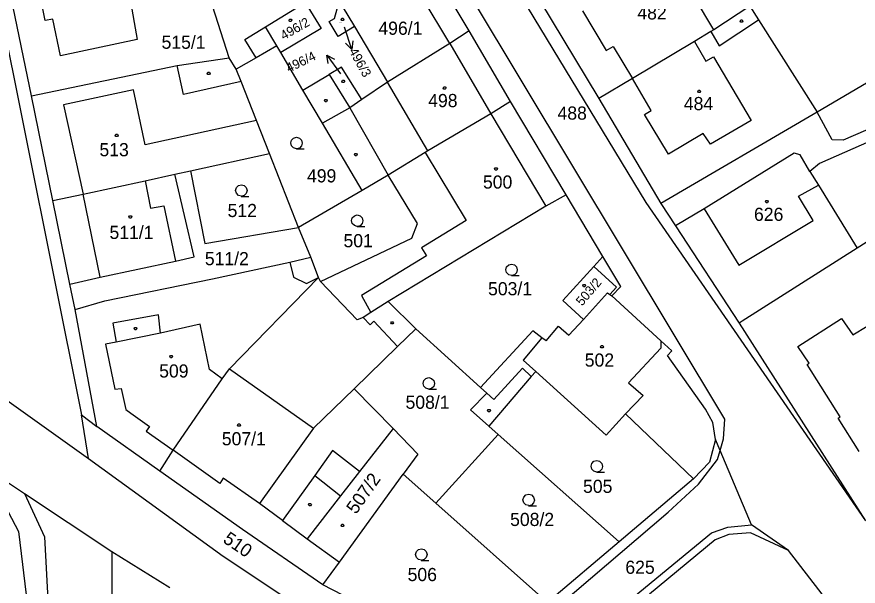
# Model space of a CAD drawing. Extents: x -621797 to -620972, y -1175539 to -1174697.
# Drawn here: x -621483.9 to -621375.1, y -1174942.7 to -1174869.1 of the extents above; entities that cross this region are included whole.
import ezdxf

# ---------------------------------------------------------------- set-up
doc = ezdxf.new("R2010")
doc.units = 0
for name, color, linetype in [('INZ mimo EON - nadz', 7, 'Continuous'), ('Rozvod plynu EON', 7, 'Continuous'), ('SDEL EON', 7, 'Continuous'), ('SDEL EON - popis', 7, 'Continuous'), ('Silnoproud EON', 7, 'Continuous'), ('Silnoproud EON - popis', 7, 'Continuous')]:
    doc.layers.add(name, color=color, linetype=linetype)

msp = doc.modelspace()

# ---------------------------------------------------------------- linework, layer by layer
at = {"layer": 'INZ mimo EON - nadz'}
for p, q in [((-621440.592, -1174873.333), (-621441.52, -1174870.48)), ((-621443.803, -1174874.072), (-621442.04, -1174876.5))]:
    msp.add_line(p, q, dxfattribs=at)
for points in [[(-621440.426, -1174872.227), (-621440.592, -1174873.333), (-621441.377, -1174872.537)], [(-621443.62, -1174875.175), (-621443.803, -1174874.072), (-621442.81, -1174874.588)]]:
    msp.add_lwpolyline(points, dxfattribs=at)
at = {"layer": 'Rozvod plynu EON'}
for points in [[(-621441.7, -1174869.31), (-621441.61, -1174869.46), (-621441.7, -1174869.61), (-621441.88, -1174869.61), (-621441.97, -1174869.46), (-621441.88, -1174869.31)], [(-621448.43, -1174869.43), (-621448.34, -1174869.58), (-621448.43, -1174869.73), (-621448.61, -1174869.73), (-621448.7, -1174869.58), (-621448.61, -1174869.43)], [(-621390.1, -1174869.53), (-621390.01, -1174869.68), (-621390.1, -1174869.83), (-621390.28, -1174869.83), (-621390.37, -1174869.68), (-621390.28, -1174869.53)], [(-621458.99, -1174876.29), (-621458.9, -1174876.44), (-621458.99, -1174876.59), (-621459.17, -1174876.59), (-621459.26, -1174876.44), (-621459.17, -1174876.29)], [(-621441.59, -1174877.32), (-621441.5, -1174877.47), (-621441.59, -1174877.62), (-621441.77, -1174877.62), (-621441.86, -1174877.47), (-621441.77, -1174877.32)], [(-621428.49, -1174878.19), (-621428.4, -1174878.34), (-621428.49, -1174878.49), (-621428.67, -1174878.49), (-621428.76, -1174878.34), (-621428.67, -1174878.19)], [(-621395.59, -1174878.61), (-621395.5, -1174878.76), (-621395.59, -1174878.91), (-621395.77, -1174878.91), (-621395.86, -1174878.76), (-621395.77, -1174878.61)], [(-621443.84, -1174879.81), (-621443.75, -1174879.96), (-621443.84, -1174880.11), (-621444.02, -1174880.11), (-621444.11, -1174879.96), (-621444.02, -1174879.81)], [(-621470.89, -1174884.3), (-621470.8, -1174884.45), (-621470.89, -1174884.6), (-621471.07, -1174884.6), (-621471.16, -1174884.45), (-621471.07, -1174884.3)], [(-621439.98, -1174886.79), (-621439.89, -1174886.94), (-621439.98, -1174887.09), (-621440.16, -1174887.09), (-621440.25, -1174886.94), (-621440.16, -1174886.79)], [(-621421.85, -1174888.63), (-621421.76, -1174888.78), (-621421.85, -1174888.93), (-621422.03, -1174888.93), (-621422.12, -1174888.78), (-621422.03, -1174888.63)], [(-621386.83, -1174892.85), (-621386.74, -1174893), (-621386.83, -1174893.15), (-621387.01, -1174893.15), (-621387.1, -1174893), (-621387.01, -1174892.85)], [(-621469.12, -1174894.83), (-621469.03, -1174894.98), (-621469.12, -1174895.13), (-621469.3, -1174895.13), (-621469.39, -1174894.98), (-621469.3, -1174894.83)], [(-621410.46, -1174903.71), (-621410.37, -1174903.86), (-621410.46, -1174904.01), (-621410.64, -1174904.01), (-621410.73, -1174903.86), (-621410.64, -1174903.71)], [(-621468.44, -1174909.27), (-621468.35, -1174909.42), (-621468.44, -1174909.57), (-621468.62, -1174909.57), (-621468.71, -1174909.42), (-621468.62, -1174909.27)], [(-621435.26, -1174908.53), (-621435.17, -1174908.68), (-621435.26, -1174908.83), (-621435.44, -1174908.83), (-621435.53, -1174908.68), (-621435.44, -1174908.53)], [(-621408.14, -1174911.62), (-621408.05, -1174911.77), (-621408.14, -1174911.92), (-621408.32, -1174911.92), (-621408.41, -1174911.77), (-621408.32, -1174911.62)], [(-621463.83, -1174912.89), (-621463.74, -1174913.04), (-621463.83, -1174913.19), (-621464.01, -1174913.19), (-621464.1, -1174913.04), (-621464.01, -1174912.89)], [(-621422.75, -1174919.88), (-621422.66, -1174920.03), (-621422.75, -1174920.18), (-621422.93, -1174920.18), (-621423.02, -1174920.03), (-621422.93, -1174919.88)], [(-621455.07, -1174921.75), (-621454.98, -1174921.9), (-621455.07, -1174922.05), (-621455.25, -1174922.05), (-621455.34, -1174921.9), (-621455.25, -1174921.75)], [(-621445.9, -1174932.03), (-621445.81, -1174932.18), (-621445.9, -1174932.33), (-621446.08, -1174932.33), (-621446.17, -1174932.18), (-621446.08, -1174932.03)], [(-621441.68, -1174934.72), (-621441.59, -1174934.87), (-621441.68, -1174935.02), (-621441.86, -1174935.02), (-621441.95, -1174934.87), (-621441.86, -1174934.72)]]:
    msp.add_lwpolyline(points, close=True, dxfattribs=at)
at = {"layer": 'SDEL EON'}
for points in [[(-621447.72, -1174886.17), (-621448.1, -1174886.07), (-621448.37, -1174885.8), (-621448.47, -1174885.43), (-621448.37, -1174885.06), (-621448.1, -1174884.79), (-621447.73, -1174884.69), (-621447.36, -1174884.79), (-621447.09, -1174885.06), (-621446.99, -1174885.44), (-621447.09, -1174885.82), (-621447.36, -1174886.09), (-621447.74, -1174886.19), (-621446.74, -1174886.19)], [(-621454.85, -1174892.31), (-621455.23, -1174892.21), (-621455.5, -1174891.94), (-621455.6, -1174891.57), (-621455.5, -1174891.2), (-621455.23, -1174890.93), (-621454.86, -1174890.83), (-621454.49, -1174890.93), (-621454.22, -1174891.2), (-621454.12, -1174891.58), (-621454.22, -1174891.96), (-621454.49, -1174892.23), (-621454.87, -1174892.33), (-621453.87, -1174892.33)], [(-621439.87, -1174896.21), (-621440.25, -1174896.11), (-621440.52, -1174895.84), (-621440.62, -1174895.47), (-621440.52, -1174895.1), (-621440.25, -1174894.83), (-621439.88, -1174894.73), (-621439.51, -1174894.83), (-621439.24, -1174895.1), (-621439.14, -1174895.48), (-621439.24, -1174895.86), (-621439.51, -1174896.13), (-621439.89, -1174896.23), (-621438.89, -1174896.23)], [(-621419.91, -1174902.56), (-621420.29, -1174902.46), (-621420.56, -1174902.19), (-621420.66, -1174901.82), (-621420.56, -1174901.45), (-621420.29, -1174901.18), (-621419.92, -1174901.08), (-621419.55, -1174901.18), (-621419.28, -1174901.45), (-621419.18, -1174901.83), (-621419.28, -1174902.21), (-621419.55, -1174902.48), (-621419.93, -1174902.58), (-621418.93, -1174902.58)], [(-621430.62, -1174917.24), (-621431, -1174917.14), (-621431.27, -1174916.87), (-621431.37, -1174916.5), (-621431.27, -1174916.13), (-621431, -1174915.86), (-621430.63, -1174915.76), (-621430.26, -1174915.86), (-621429.99, -1174916.13), (-621429.89, -1174916.51), (-621429.99, -1174916.89), (-621430.26, -1174917.16), (-621430.64, -1174917.26), (-621429.64, -1174917.26)], [(-621408.9, -1174927.96), (-621409.28, -1174927.86), (-621409.55, -1174927.59), (-621409.65, -1174927.22), (-621409.55, -1174926.85), (-621409.28, -1174926.58), (-621408.91, -1174926.48), (-621408.54, -1174926.58), (-621408.27, -1174926.85), (-621408.17, -1174927.23), (-621408.27, -1174927.61), (-621408.54, -1174927.88), (-621408.92, -1174927.98), (-621407.92, -1174927.98)], [(-621417.7, -1174932.31), (-621418.08, -1174932.21), (-621418.35, -1174931.94), (-621418.45, -1174931.57), (-621418.35, -1174931.2), (-621418.08, -1174930.93), (-621417.71, -1174930.83), (-621417.34, -1174930.93), (-621417.07, -1174931.2), (-621416.97, -1174931.58), (-621417.07, -1174931.96), (-621417.34, -1174932.23), (-621417.72, -1174932.33), (-621416.72, -1174932.33)], [(-621431.58, -1174939.36), (-621431.96, -1174939.26), (-621432.23, -1174938.99), (-621432.33, -1174938.62), (-621432.23, -1174938.25), (-621431.96, -1174937.98), (-621431.59, -1174937.88), (-621431.22, -1174937.98), (-621430.95, -1174938.25), (-621430.85, -1174938.63), (-621430.95, -1174939.01), (-621431.22, -1174939.28), (-621431.6, -1174939.38), (-621430.6, -1174939.38)]]:
    msp.add_lwpolyline(points, dxfattribs=at)
at = {"layer": 'SDEL EON - popis'}
for p, q in [((-621461.85, -1174795.25), (-621402.58, -1174893.11)), ((-621392.36, -1174921.13), (-621457.84, -1174812.05)), ((-621496.37, -1174817.09), (-621475.54, -1174920.55)), ((-621393.76, -1174870.81), (-621400.21, -1174860.03)), ((-621427.89, -1174872.59), (-621432.38, -1174865.12)), ((-621410.77, -1174868.36), (-621407.68, -1174873.5)), ((-621450.25, -1174872.87), (-621451.73, -1174870.41)), ((-621440.25, -1174870.4), (-621435.96, -1174877.59)), ((-621393.09, -1174872.86), (-621387.99, -1174869.52)), ((-621394.15, -1174871.04), (-621393.09, -1174872.86)), ((-621427.89, -1174872.59), (-621422.62, -1174881.67)), ((-621396.27, -1174872.3), (-621394.83, -1174874.88)), ((-621407.68, -1174873.5), (-621406.78, -1174872.96)), ((-621406.78, -1174872.96), (-621404.31, -1174877.11)), ((-621394.83, -1174874.88), (-621393.84, -1174874.3)), ((-621393.84, -1174874.3), (-621388.96, -1174882.51)), ((-621462.33, -1174879.15), (-621463.14, -1174875.44)), ((-621446.9, -1174878.59), (-621443.51, -1174876.59)), ((-621454.89, -1174877.5), (-621462.33, -1174879.15)), ((-621430.75, -1174886.47), (-621435.96, -1174877.59)), ((-621401.87, -1174881.25), (-621404.31, -1174877.11)), ((-621468.79, -1174878.58), (-621477.87, -1174880.51)), ((-621467.28, -1174885.68), (-621468.79, -1174878.58)), ((-621477.87, -1174880.51), (-621475.29, -1174892.05)), ((-621440.85, -1174880.87), (-621435.89, -1174889.58)), ((-621402.75, -1174881.74), (-621401.87, -1174881.25)), ((-621422.62, -1174881.67), (-621415.51, -1174893.59)), ((-621399.63, -1174886.87), (-621402.75, -1174881.74)), ((-621452.92, -1174882.52), (-621467.28, -1174885.68)), ((-621388.96, -1174882.51), (-621394.22, -1174885.59)), ((-621395.15, -1174884.2), (-621399.63, -1174886.87)), ((-621394.22, -1174885.59), (-621395.15, -1174884.2)), ((-621431.09, -1174886.68), (-621425.81, -1174895.47)), ((-621467.31, -1174890.31), (-621466.6, -1174893.88)), ((-621382.81, -1174892.32), (-621380.25, -1174890.89)), ((-621473.12, -1174902.78), (-621475.29, -1174892.05)), ((-621402.58, -1174893.11), (-621374.18, -1174934.27)), ((-621380.93, -1174895.46), (-621382.81, -1174892.32)), ((-621466.6, -1174893.88), (-621464.9, -1174893.57)), ((-621464.9, -1174893.57), (-621463.36, -1174900.69)), ((-621395.03, -1174893.93), (-621390.56, -1174901.21)), ((-621425.81, -1174895.47), (-621431.56, -1174898.98)), ((-621390.56, -1174901.21), (-621380.93, -1174895.46)), ((-621431.56, -1174898.98), (-621430.92, -1174900.04)), ((-621448.61, -1174900.84), (-621448.1, -1174902.76)), ((-621430.92, -1174900.04), (-621439.31, -1174905.13)), ((-621409.31, -1174901.4), (-621406.37, -1174904.09)), ((-621448.1, -1174902.76), (-621446.44, -1174903.59)), ((-621446.44, -1174903.59), (-621444.87, -1174902.81)), ((-621406.37, -1174904.09), (-621407.22, -1174905.03)), ((-621439.31, -1174905.13), (-621438.12, -1174907.35)), ((-621465.59, -1174907.63), (-621471.46, -1174908.74)), ((-621465.33, -1174910.02), (-621465.59, -1174907.63)), ((-621439.1, -1174907.98), (-621438.21, -1174908.92)), ((-621438.21, -1174908.92), (-621437.74, -1174908.48)), ((-621437.74, -1174908.48), (-621434.65, -1174911.75)), ((-621471.46, -1174908.74), (-621471.06, -1174911.16)), ((-621460.2, -1174908.87), (-621465.33, -1174910.02)), ((-621458.96, -1174914.69), (-621460.2, -1174908.87)), ((-621465.33, -1174910.02), (-621471.06, -1174911.16)), ((-621416, -1174910.63), (-621418.44, -1174913.49)), ((-621471.06, -1174911.16), (-621472.41, -1174911.43)), ((-621472.41, -1174911.43), (-621471.23, -1174917.24)), ((-621400.64, -1174911.01), (-621400.64, -1174911.94)), ((-621400.64, -1174911.94), (-621404.8, -1174916.45)), ((-621418.44, -1174913.49), (-621416.8, -1174914.97)), ((-621457.34, -1174915.93), (-621458.96, -1174914.69)), ((-621456.4, -1174914.62), (-621445.54, -1174922.29)), ((-621418.53, -1174914.55), (-621422.23, -1174918.59)), ((-621417.37, -1174915.6), (-621418.53, -1174914.55)), ((-621471.23, -1174917.24), (-621470.38, -1174917.16)), ((-621470.38, -1174917.16), (-621469.8, -1174919.87)), ((-621445.54, -1174922.29), (-621440.29, -1174917.22)), ((-621404.8, -1174916.45), (-621402.93, -1174918.08)), ((-621422.23, -1174918.59), (-621423.11, -1174917.78)), ((-621402.93, -1174918.08), (-621405.18, -1174920.43)), ((-621469.8, -1174919.87), (-621469.16, -1174920.37)), ((-621469.16, -1174920.37), (-621466.74, -1174922.09)), ((-621392.51, -1174923.66), (-621392.36, -1174921.13)), ((-621466.74, -1174922.09), (-621467.16, -1174922.66)), ((-621467.16, -1174922.66), (-621463.66, -1174925.15)), ((-621445.54, -1174922.29), (-621452.5, -1174932.03)), ((-621392.97, -1174925.2), (-621392.51, -1174923.66)), ((-621457.66, -1174929.46), (-621463.66, -1174925.15)), ((-621393.3, -1174926.33), (-621392.97, -1174925.2)), ((-621395.75, -1174929.52), (-621393.3, -1174926.33)), ((-621439.57, -1174927.9), (-621442.03, -1174931.06)), ((-621457.22, -1174928.75), (-621457.66, -1174929.46)), ((-621452.5, -1174932.03), (-621457.22, -1174928.75)), ((-621445.38, -1174928.42), (-621442.03, -1174931.06)), ((-621399.66, -1174933.17), (-621395.75, -1174929.52)), ((-621482.89, -1174930.73), (-621480.32, -1174936.32)), ((-621442.03, -1174931.06), (-621446.33, -1174936.58)), ((-621449.54, -1174934.21), (-621452.5, -1174932.03)), ((-621421.45, -1174951.71), (-621399.66, -1174933.17)), ((-621394.09, -1174935.82), (-621391.98, -1174935.1)), ((-621391.98, -1174935.1), (-621388.9, -1174934.77)), ((-621480.32, -1174936.32), (-621479.72, -1174947)), ((-621418.87, -1174956.17), (-621394.09, -1174935.82)), ((-621471.62, -1174938.22), (-621471.6, -1174947.02))]:
    msp.add_line(p, q, dxfattribs=at)
at = {"layer": 'Silnoproud EON'}
for p, q in [((-621480.21, -1174869.59), (-621482.45, -1174858.66)), ((-621425.39, -1174870.96), (-621432.52, -1174858.98)), ((-621481.99, -1174879.34), (-621486.02, -1174859.72)), ((-621470.18, -1174861.13), (-621468.34, -1174872.07)), ((-621350.07, -1174863.62), (-621380.4, -1174881.45)), ((-621456.42, -1174874.43), (-621459.66, -1174864.35)), ((-621416.3, -1174866.94), (-621408.65, -1174879.68)), ((-621451.73, -1174870.41), (-621446.59, -1174867.29)), ((-621446.59, -1174867.29), (-621444.54, -1174870.63)), ((-621442.82, -1174869.35), (-621442.45, -1174868.11)), ((-621441.83, -1174867.74), (-621440.25, -1174870.4)), ((-621389.1, -1174867.76), (-621393.76, -1174870.81)), ((-621389.1, -1174867.76), (-621387.99, -1174869.52)), ((-621443.49, -1174869.75), (-621442.82, -1174869.35)), ((-621479.23, -1174869.43), (-621480.21, -1174869.59)), ((-621478.22, -1174874.17), (-621479.23, -1174869.43)), ((-621454.41, -1174872.04), (-621451.73, -1174870.41)), ((-621442.35, -1174871.65), (-621443.49, -1174869.75)), ((-621440.25, -1174870.4), (-621442.35, -1174871.65)), ((-621387.99, -1174869.52), (-621380.4, -1174881.45)), ((-621444.54, -1174870.63), (-621449.74, -1174873.74)), ((-621425.39, -1174870.96), (-621427.89, -1174872.59)), ((-621420.06, -1174880.06), (-621425.39, -1174870.96)), ((-621394.15, -1174871.04), (-621396.27, -1174872.3)), ((-621393.76, -1174870.81), (-621394.15, -1174871.04)), ((-621468.34, -1174872.07), (-621478.22, -1174874.17)), ((-621452.96, -1174874.43), (-621454.41, -1174872.04)), ((-621427.89, -1174872.59), (-621435.96, -1174877.59)), ((-621396.27, -1174872.3), (-621404.31, -1174877.11)), ((-621450.25, -1174872.87), (-621452.96, -1174874.43)), ((-621449.74, -1174873.74), (-621450.25, -1174872.87)), ((-621350.1, -1174873.33), (-621377.07, -1174885.08)), ((-621463.14, -1174875.44), (-621456.42, -1174874.43)), ((-621455.52, -1174875.9), (-621456.42, -1174874.43)), ((-621452.96, -1174874.43), (-621455.52, -1174875.9)), ((-621446.9, -1174878.59), (-621449.74, -1174873.74)), ((-621481.99, -1174879.34), (-621463.14, -1174875.44)), ((-621441.9, -1174875.64), (-621443.51, -1174876.59)), ((-621439.28, -1174879.82), (-621441.9, -1174875.64)), ((-621454.89, -1174877.5), (-621455.52, -1174875.9)), ((-621443.51, -1174876.59), (-621440.85, -1174880.87)), ((-621452.92, -1174882.52), (-621454.89, -1174877.5)), ((-621435.96, -1174877.59), (-621439.28, -1174879.82)), ((-621404.31, -1174877.11), (-621408.65, -1174879.68)), ((-621444.37, -1174882.89), (-621446.9, -1174878.59)), ((-621359.28, -1174878.9), (-621380.1, -1174888.08)), ((-621479.25, -1174892.85), (-621481.99, -1174879.34)), ((-621439.28, -1174879.82), (-621440.85, -1174880.87)), ((-621420.06, -1174880.06), (-621422.62, -1174881.67)), ((-621412.86, -1174892.15), (-621420.06, -1174880.06)), ((-621408.65, -1174879.68), (-621400.61, -1174893.25)), ((-621440.85, -1174880.87), (-621444.37, -1174882.89)), ((-621422.62, -1174881.67), (-621430.75, -1174886.47)), ((-621380.4, -1174881.45), (-621400.61, -1174893.25)), ((-621378.47, -1174885.02), (-621380.4, -1174881.45)), ((-621451.24, -1174886.81), (-621452.92, -1174882.52)), ((-621439.22, -1174891.57), (-621444.37, -1174882.89)), ((-621377.07, -1174885.08), (-621378.47, -1174885.02)), ((-621431.09, -1174886.68), (-621435.89, -1174889.58)), ((-621430.75, -1174886.47), (-621431.09, -1174886.68)), ((-621383.38, -1174886.75), (-621395.03, -1174893.93)), ((-621382.6, -1174886.97), (-621383.38, -1174886.75)), ((-621461.45, -1174889.04), (-621451.24, -1174886.81)), ((-621447.49, -1174896.36), (-621451.24, -1174886.81)), ((-621381.37, -1174889.11), (-621382.6, -1174886.97)), ((-621380.1, -1174888.08), (-621381.37, -1174889.11)), ((-621467.31, -1174890.31), (-621463.44, -1174889.47)), ((-621463.44, -1174889.47), (-621461.45, -1174889.04)), ((-621460.96, -1174900.17), (-621463.44, -1174889.47)), ((-621461.45, -1174889.04), (-621459.6, -1174898.44)), ((-621435.89, -1174889.58), (-621439.22, -1174891.57)), ((-621432.07, -1174895.86), (-621435.89, -1174889.58)), ((-621381.37, -1174889.11), (-621380.25, -1174890.89)), ((-621475.29, -1174892.05), (-621467.31, -1174890.31)), ((-621380.25, -1174890.89), (-621375.24, -1174899.03)), ((-621479.25, -1174892.85), (-621475.29, -1174892.05)), ((-621439.22, -1174891.57), (-621447.49, -1174896.36)), ((-621412.86, -1174892.15), (-621415.51, -1174893.59)), ((-621408.12, -1174900.09), (-621412.86, -1174892.15)), ((-621477.03, -1174903.67), (-621479.25, -1174892.85)), ((-621400.61, -1174893.25), (-621398.72, -1174896.16)), ((-621415.51, -1174893.59), (-621435.88, -1174905.92)), ((-621395.03, -1174893.93), (-621398.72, -1174896.16)), ((-621459.6, -1174898.44), (-621447.49, -1174896.36)), ((-621445.88, -1174900.2), (-621447.49, -1174896.36)), ((-621432.8, -1174897.72), (-621432.07, -1174895.86)), ((-621398.72, -1174896.16), (-621390.48, -1174908.73)), ((-621370.51, -1174896.02), (-621375.24, -1174899.03)), ((-621444.62, -1174903.33), (-621432.8, -1174897.72)), ((-621375.24, -1174899.03), (-621390.1, -1174908.48)), ((-621473.12, -1174902.78), (-621463.36, -1174900.69)), ((-621463.36, -1174900.69), (-621460.96, -1174900.17)), ((-621458.6, -1174902.99), (-621448.61, -1174900.84)), ((-621448.61, -1174900.84), (-621445.88, -1174900.2)), ((-621444.87, -1174902.81), (-621445.88, -1174900.2)), ((-621408.12, -1174900.09), (-621409.31, -1174901.4)), ((-621405.8, -1174903.98), (-621408.12, -1174900.09)), ((-621409.31, -1174901.4), (-621413.31, -1174905.78)), ((-621477.03, -1174903.67), (-621473.12, -1174902.78)), ((-621472.49, -1174905.82), (-621458.6, -1174902.99)), ((-621456.4, -1174914.62), (-621444.87, -1174902.81)), ((-621444.62, -1174903.33), (-621444.87, -1174902.81)), ((-621476.36, -1174906.94), (-621477.03, -1174903.67)), ((-621439.89, -1174908.31), (-621444.62, -1174903.33)), ((-621406.98, -1174905.21), (-621405.8, -1174903.98)), ((-621410.63, -1174908.23), (-621407.51, -1174904.81)), ((-621407.51, -1174904.81), (-621407.22, -1174905.03)), ((-621407.22, -1174905.03), (-621406.98, -1174905.21)), ((-621400.64, -1174911.01), (-621406.98, -1174905.21)), ((-621476.36, -1174906.94), (-621472.49, -1174905.82)), ((-621435.88, -1174905.92), (-621438.12, -1174907.35)), ((-621432.3, -1174909.45), (-621435.88, -1174905.92)), ((-621413.31, -1174905.78), (-621410.63, -1174908.23)), ((-621473.53, -1174922.09), (-621476.36, -1174906.94)), ((-621438.12, -1174907.35), (-621439.1, -1174907.98)), ((-621439.1, -1174907.98), (-621439.89, -1174908.31)), ((-621412.51, -1174910.29), (-621410.63, -1174908.23)), ((-621390.1, -1174908.48), (-621390.48, -1174908.73)), ((-621382.92, -1174911.73), (-621377.27, -1174908.11)), ((-621377.27, -1174908.11), (-621375.81, -1174910.25)), ((-621432.3, -1174909.45), (-621434.65, -1174911.75)), ((-621423.93, -1174917.03), (-621432.3, -1174909.45)), ((-621415.47, -1174911), (-621413.85, -1174909.12)), ((-621413.85, -1174909.12), (-621412.51, -1174910.29)), ((-621390.48, -1174908.73), (-621374.18, -1174934.27)), ((-621375.81, -1174910.25), (-621373.96, -1174909.13)), ((-621417.19, -1174909.7), (-621423.93, -1174917.03)), ((-621416, -1174910.63), (-621417.19, -1174909.7)), ((-621415.47, -1174911), (-621416, -1174910.63)), ((-621434.65, -1174911.75), (-621440.29, -1174917.22)), ((-621399.19, -1174912.3), (-621400.64, -1174911.01)), ((-621381.46, -1174913.91), (-621382.92, -1174911.73)), ((-621399.77, -1174912.9), (-621399.19, -1174912.3)), ((-621394.85, -1174919.83), (-621399.77, -1174912.9)), ((-621381.72, -1174914.08), (-621381.46, -1174913.91)), ((-621457.34, -1174915.93), (-621456.4, -1174914.62)), ((-621416.8, -1174914.97), (-621417.37, -1174915.6)), ((-621407.69, -1174923.21), (-621416.8, -1174914.97)), ((-621377.44, -1174920.84), (-621381.72, -1174914.08)), ((-621489.4, -1174915.7), (-621474.63, -1174926.2)), ((-621463.66, -1174925.15), (-621457.34, -1174915.93)), ((-621417.37, -1174915.6), (-621422.86, -1174922.04)), ((-621440.29, -1174917.22), (-621435.24, -1174922.34)), ((-621423.11, -1174917.78), (-621423.93, -1174917.03)), ((-621425.25, -1174919.92), (-621423.11, -1174917.78)), ((-621422.86, -1174922.04), (-621425.25, -1174919.92)), ((-621405.18, -1174920.43), (-621407.69, -1174923.21)), ((-621396.4, -1174928.83), (-621405.18, -1174920.43)), ((-621393.92, -1174921.56), (-621394.85, -1174919.83)), ((-621474.63, -1174926.2), (-621475.54, -1174920.55)), ((-621475.54, -1174920.55), (-621473.53, -1174922.09)), ((-621393.58, -1174923.76), (-621393.92, -1174921.56)), ((-621377.69, -1174921), (-621377.44, -1174920.84)), ((-621374.99, -1174925.32), (-621377.69, -1174921)), ((-621465.41, -1174927.87), (-621473.53, -1174922.09)), ((-621435.24, -1174922.34), (-621439.57, -1174927.9)), ((-621435.24, -1174922.34), (-621432.05, -1174925.67)), ((-621421.66, -1174923.11), (-621422.86, -1174922.04)), ((-621429.73, -1174931.98), (-621421.66, -1174923.11)), ((-621406.03, -1174936.98), (-621421.66, -1174923.11)), ((-621393.58, -1174923.76), (-621394.34, -1174926.68)), ((-621392.97, -1174925.2), (-621393.58, -1174923.76)), ((-621491.48, -1174925.04), (-621482.89, -1174930.73)), ((-621465.41, -1174927.87), (-621463.66, -1174925.15)), ((-621443.07, -1174925.17), (-621445.38, -1174928.42)), ((-621439.57, -1174927.9), (-621443.07, -1174925.17)), ((-621432.05, -1174925.67), (-621433.93, -1174928.25)), ((-621388.9, -1174934.77), (-621392.97, -1174925.2)), ((-621474.63, -1174926.2), (-621457.21, -1174938.83)), ((-621394.34, -1174926.68), (-621396.4, -1174928.83)), ((-621454.71, -1174935.38), (-621465.41, -1174927.87)), ((-621487.55, -1174928.32), (-621483.68, -1174935.67)), ((-621445.38, -1174928.42), (-621449.54, -1174934.21)), ((-621442.19, -1174939.61), (-621433.93, -1174928.25)), ((-621433.93, -1174928.25), (-621429.73, -1174931.98)), ((-621396.4, -1174928.83), (-621406.03, -1174936.98)), ((-621482.89, -1174930.73), (-621471.62, -1174938.22)), ((-621429.73, -1174931.98), (-621415.27, -1174944.81)), ((-621449.54, -1174934.21), (-621446.33, -1174936.58)), ((-621483.68, -1174935.67), (-621482.27, -1174947.07)), ((-621444.34, -1174942.56), (-621454.71, -1174935.38)), ((-621384.13, -1174938.12), (-621388.9, -1174934.77)), ((-621446.33, -1174936.58), (-621442.19, -1174939.61)), ((-621393.6, -1174936.71), (-621402.08, -1174943.74)), ((-621391.83, -1174936.02), (-621393.6, -1174936.71)), ((-621389.02, -1174935.84), (-621391.83, -1174936.02)), ((-621384.13, -1174938.12), (-621389.02, -1174935.84)), ((-621406.03, -1174936.98), (-621415.27, -1174944.81)), ((-621471.62, -1174938.22), (-621464.11, -1174942.87)), ((-621457.21, -1174938.83), (-621446.7, -1174945.8)), ((-621364.82, -1174963.05), (-621384.13, -1174938.12)), ((-621444.34, -1174942.56), (-621442.19, -1174939.61)), ((-621426.26, -1174951.7), (-621444.34, -1174942.56))]:
    msp.add_line(p, q, dxfattribs=at)

# ---------------------------------------------------------------- texts
at = {"layer": 'INZ mimo EON - nadz'}
for s, rotation, p in [('496/4', 26.01228, (-621448.717, -1174876.359)), ('496/3', 299.02667, (-621440.985, -1174873.55))]:
    msp.add_text(s, height=1.2, rotation=rotation, dxfattribs=at).set_placement(p)
at = {"layer": 'Silnoproud EON - popis'}
for s, height, p in [('482', 1.7, (-621403.663, -1174869.47)), ('496/3', 0.1, (-621442.206, -1174869.93)), ('496/1', 1.7, (-621437.143, -1174871.45)), ('515/1', 1.7, (-621465.173, -1174873.26)), ('498', 1.7, (-621430.703, -1174880.8)), ('484', 1.7, (-621397.653, -1174881.19)), ('488', 1.7, (-621413.983, -1174882.42)), ('513', 1.7, (-621473.203, -1174887.15)), ('499', 1.7, (-621446.373, -1174890.53)), ('500', 1.7, (-621423.623, -1174891.33)), ('512', 1.7, (-621456.633, -1174895.01)), ('626', 1.7, (-621388.583, -1174895.5)), ('511/1', 1.7, (-621471.906, -1174897.84)), ('501', 1.7, (-621441.653, -1174898.91)), ('511/2', 1.7, (-621459.578, -1174901.23)), ('503/1', 1.7, (-621422.963, -1174905.12)), ('502', 1.7, (-621410.463, -1174914.34)), ('509', 1.7, (-621465.483, -1174915.75)), ('508/1', 1.7, (-621433.633, -1174919.79)), ('507/1', 1.7, (-621457.383, -1174924.51)), ('505', 1.7, (-621410.683, -1174930.66)), ('508/2', 1.7, (-621420.113, -1174934.94)), ('625', 1.7, (-621405.213, -1174941.12)), ('506', 1.7, (-621433.363, -1174942.06))]:
    msp.add_text(s, height=height, dxfattribs=at).set_placement(p)
for s, height, rotation, p in [('496/2', 1.2, 29.67921, (-621449.384, -1174872.167)), ('496/4', 0.1, 304.18329, (-621441.472, -1174878.242)), ('503/2', 1.2, 49.50355, (-621410.811, -1174906.573)), ('507/2', 1.7, 54.88936, (-621440.033, -1174933.516)), ('510', 1.7, 325.7838, (-621457.354, -1174936.963))]:
    msp.add_text(s, height=height, rotation=rotation, dxfattribs=at).set_placement(p)

doc.saveas('drawing.dxf')
